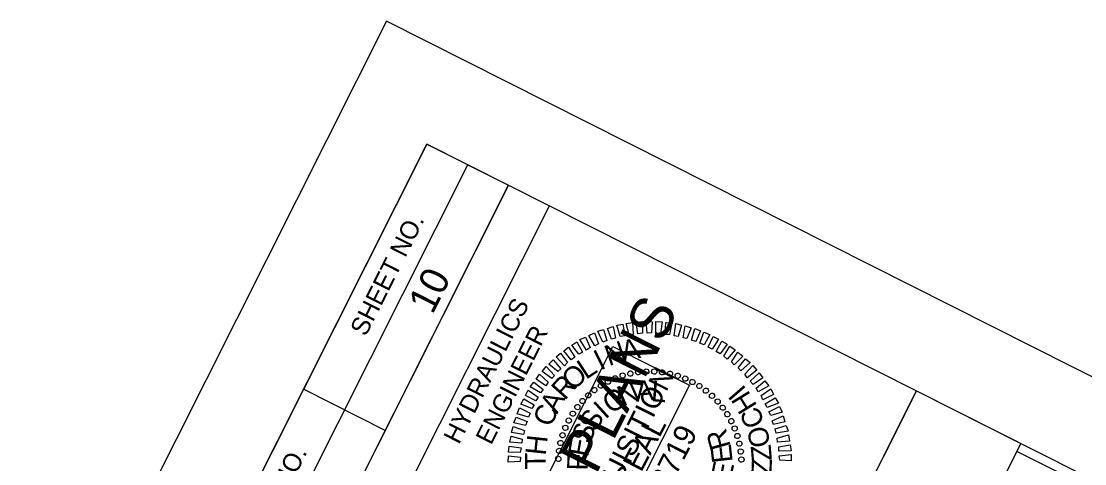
# Model space of a CAD drawing. Extents: x 2010322 to 2012069, y 441674 to 443687.
# Drawn here: x 2010986.8 to 2011277.9, y 443566.2 to 443687.1 of the extents above; entities that cross this region are included whole.
import ezdxf

# ---------------------------------------------------------------- set-up
doc = ezdxf.new("R2010")
doc.units = 0
for name, color, linetype in [('Sheet Clip Boundary CELL', 7, 'Continuous'), ('Sheet Data Field CELL', 7, 'Continuous'), ('Sheet Plan And Profile CELL', 7, 'Continuous'), ('Sheet Plot Border Outside CELL', 7, 'Continuous'), ('Sheet Professional Seal CELL', 7, 'Continuous'), ('Sheet Profile Grid Minor CELL', 7, 'Continuous'), ('Sheet Sticker Exception Certification CELL', 7, 'Continuous'), ('Sheet Sticker Incomplete CELL', 7, 'Continuous')]:
    doc.layers.add(name, color=color, linetype=linetype)

msp = doc.modelspace()

# ---------------------------------------------------------------- linework, layer by layer
at = {"layer": 'Sheet Clip Boundary CELL'}
msp.add_lwpolyline([(2011359.68, 441843.44), (2012033.06, 443180.92), (2011922.92, 443238.13), (2011759.16, 443078.9), (2011595.22, 443247.25), (2011606.93, 443258.94), (2011612.2, 443362.21), (2011388.82, 443474.46), (2011348.46, 443524.76), (2011259.26, 443569.48), (2011170.42, 443393.01), (2011067.41, 443444.87), (2010977.45, 443266.18), (2010917.88, 443296.17), (2010676.94, 442817.58), (2010544.65, 442554.81), (2010423.28, 442313.75), (2010551.1, 442249.4)], close=True, dxfattribs=at)
at = {"layer": 'Sheet Plan And Profile CELL'}
for p, q in [((2011019.05, 443469.21), (2011109.01, 443647.9)), ((2011030.22, 443463.59), (2011120.17, 443642.28)), ((2011064.12, 443586.53), (2011086.45, 443575.29))]:
    msp.add_line(p, q, dxfattribs=at)
for points in [[(2011097.8, 443653.54), (2010423.28, 442313.75), (2011361.14, 441841.59), (2012035.65, 443181.38)], [(2011007.84, 443474.86), (2011097.8, 443653.54), (2011120.17, 443642.28), (2011030.22, 443463.59)], [(2011086.37, 443547.34), (2011131.34, 443636.65), (2011231.82, 443586.07), (2011186.86, 443496.75)]]:
    msp.add_lwpolyline(points, close=True, dxfattribs=at)
at = {"layer": 'Sheet Plot Border Outside CELL'}
msp.add_lwpolyline([(2011304.77, 441674.04), (2012069.22, 443192.47), (2011086.71, 443687.11), (2010322.26, 442168.69)], close=True, dxfattribs=at)
at = {"layer": 'Sheet Professional Seal CELL'}
for p, q in [((2011151.37, 443590.28), (2011151.37, 443590.28)), ((2011153.52, 443590.88), (2011153.52, 443590.88)), ((2011155.64, 443591.21), (2011155.64, 443591.21)), ((2011157.86, 443591.38), (2011157.86, 443591.38)), ((2011160.05, 443591.4), (2011160.05, 443591.4)), ((2011162.19, 443591.21), (2011162.19, 443591.21)), ((2011164.34, 443590.8), (2011164.34, 443590.8)), ((2011166.48, 443590.17), (2011166.48, 443590.17)), ((2011145.41, 443587.57), (2011145.41, 443587.57)), ((2011147.34, 443588.62), (2011147.34, 443588.62)), ((2011149.33, 443589.57), (2011149.33, 443589.57)), ((2011168.54, 443589.47), (2011168.54, 443589.47)), ((2011170.53, 443588.53), (2011170.53, 443588.53)), ((2011172.42, 443587.41), (2011172.42, 443587.41)), ((2011141.94, 443584.9), (2011141.94, 443584.9)), ((2011143.64, 443586.28), (2011143.64, 443586.28)), ((2011174.19, 443586.13), (2011174.19, 443586.13)), ((2011175.86, 443584.78), (2011175.86, 443584.78)), ((2011139.02, 443581.66), (2011139.02, 443581.66)), ((2011140.37, 443583.34), (2011140.37, 443583.34)), ((2011177.42, 443583.21), (2011177.42, 443583.21)), ((2011178.8, 443581.51), (2011178.8, 443581.51)), ((2011137.74, 443579.9), (2011137.74, 443579.9)), ((2011180.09, 443579.74), (2011180.09, 443579.74)), ((2011135.68, 443576.01), (2011135.68, 443576.01)), ((2011136.62, 443578), (2011136.62, 443578)), ((2011181.14, 443577.81), (2011181.14, 443577.81)), ((2011182.1, 443575.82), (2011182.1, 443575.82)), ((2011134.98, 443573.96), (2011134.98, 443573.96)), ((2011182.81, 443573.78), (2011182.81, 443573.78)), ((2011133.94, 443569.67), (2011133.94, 443569.67)), ((2011134.35, 443571.81), (2011134.35, 443571.81)), ((2011183.4, 443571.63), (2011183.4, 443571.63)), ((2011183.73, 443569.51), (2011183.73, 443569.51)), ((2011133.75, 443567.52), (2011133.75, 443567.52)), ((2011183.91, 443567.29), (2011183.91, 443567.29)), ((2011158.84, 443566.31), (2011158.84, 443566.31))]:
    msp.add_line(p, q, dxfattribs=at)
for points in [[(2011153.16, 443601.41), (2011152.39, 443604.54), (2011154.11, 443604.74), (2011154.28, 443601.52)], [(2011155.58, 443601.65), (2011155.08, 443604.87), (2011156.84, 443605.05), (2011156.79, 443601.83)], [(2011158.13, 443601.82), (2011157.83, 443605.11), (2011159.5, 443604.99), (2011159.25, 443601.93)], [(2011160.5, 443601.75), (2011160.49, 443605.06), (2011162.21, 443604.92), (2011161.71, 443601.7)], [(2011163, 443601.5), (2011163.21, 443604.81), (2011164.85, 443604.6), (2011164.17, 443601.47)], [(2011165.51, 443601.13), (2011165.92, 443604.51), (2011167.53, 443604.03), (2011166.6, 443600.97)], [(2011143.74, 443598.37), (2011142.12, 443601.26), (2011143.69, 443601.93), (2011144.8, 443598.91)], [(2011145.98, 443599.37), (2011144.58, 443602.38), (2011146.19, 443602.91), (2011147.08, 443599.89)], [(2011148.35, 443600.2), (2011147.22, 443603.17), (2011148.83, 443603.71), (2011149.41, 443600.51)], [(2011150.75, 443600.95), (2011149.77, 443604.02), (2011151.45, 443604.35), (2011151.96, 443601.12)], [(2011167.92, 443600.59), (2011168.49, 443603.83), (2011170.14, 443603.33), (2011168.99, 443600.38)], [(2011170.27, 443599.91), (2011171.1, 443603.13), (2011172.69, 443602.5), (2011171.43, 443599.55)], [(2011172.55, 443599.1), (2011173.65, 443602.18), (2011175.21, 443601.51), (2011173.66, 443598.65)], [(2011139.4, 443596.08), (2011137.46, 443598.57), (2011138.89, 443599.53), (2011140.36, 443596.66)], [(2011141.48, 443597.22), (2011139.68, 443600.09), (2011141.2, 443600.77), (2011142.51, 443597.93)], [(2011174.8, 443598.02), (2011176.13, 443600.99), (2011177.65, 443600.23), (2011175.87, 443597.48)], [(2011177.01, 443596.85), (2011178.56, 443599.71), (2011179.99, 443598.88), (2011178.04, 443596.22)], [(2011135.48, 443592.96), (2011133.18, 443595.41), (2011134.35, 443596.39), (2011136.31, 443593.83)], [(2011137.34, 443594.55), (2011135.26, 443596.99), (2011136.59, 443598.06), (2011138.32, 443595.28)], [(2011179.04, 443595.55), (2011180.75, 443598.27), (2011182.18, 443597.33), (2011180, 443594.79)], [(2011181.14, 443594.05), (2011182.89, 443596.63), (2011184.25, 443595.56), (2011181.9, 443593.22)], [(2011133.66, 443591.36), (2011131.23, 443593.42), (2011132.37, 443594.58), (2011134.45, 443592.14)], [(2011182.99, 443592.39), (2011184.97, 443594.86), (2011186.28, 443593.81), (2011183.75, 443591.56)], [(2011184.8, 443590.64), (2011187, 443593), (2011188.09, 443591.72), (2011185.49, 443589.67)], [(2011130.36, 443587.48), (2011127.71, 443589.32), (2011128.67, 443590.68), (2011131.04, 443588.48)], [(2011132, 443589.51), (2011129.32, 443591.42), (2011130.44, 443592.75), (2011132.7, 443590.33)], [(2011186.31, 443588.75), (2011188.73, 443591.01), (2011189.78, 443589.64), (2011187.07, 443587.81)], [(2011128.93, 443585.51), (2011126.11, 443587.15), (2011127.12, 443588.49), (2011129.64, 443586.5)], [(2011187.92, 443586.83), (2011190.32, 443588.81), (2011191.36, 443587.44), (2011188.5, 443585.86)], [(2011127.67, 443583.35), (2011124.77, 443584.81), (2011125.55, 443586.26), (2011128.25, 443584.4)], [(2011189.3, 443584.79), (2011191.9, 443586.61), (2011192.7, 443585.09), (2011189.74, 443583.67)], [(2011190.41, 443582.55), (2011193.14, 443584.2), (2011194.01, 443582.7), (2011190.97, 443581.54)], [(2011125.64, 443578.88), (2011122.54, 443579.83), (2011123.12, 443581.44), (2011126.05, 443580.02)], [(2011126.54, 443581.23), (2011123.53, 443582.47), (2011124.32, 443583.92), (2011127.13, 443582.28)], [(2011191.43, 443580.35), (2011194.34, 443581.8), (2011195.01, 443580.23), (2011191.92, 443579.32)], [(2011124.83, 443576.6), (2011121.61, 443577.33), (2011122.22, 443578.87), (2011125.24, 443577.74)], [(2011192.34, 443577.94), (2011195.32, 443579.29), (2011195.79, 443577.66), (2011192.7, 443576.86)], [(2011124.24, 443574.21), (2011120.96, 443574.69), (2011121.41, 443576.37), (2011124.49, 443575.26)], [(2011193.16, 443575.68), (2011196.12, 443576.65), (2011196.65, 443575.04), (2011193.36, 443574.51)], [(2011123.75, 443571.78), (2011120.55, 443572.1), (2011120.84, 443573.68), (2011123.91, 443572.87)], [(2011193.65, 443573.19), (2011196.76, 443574.03), (2011197.09, 443572.36), (2011193.8, 443572.05)], [(2011123.36, 443569.23), (2011120.18, 443569.37), (2011120.32, 443570.98), (2011123.65, 443570.48)], [(2011194.13, 443570.82), (2011197.24, 443571.33), (2011197.51, 443569.74), (2011194.18, 443569.57)], [(2011123.31, 443566.79), (2011120.09, 443566.62), (2011120.16, 443568.32), (2011123.4, 443567.98)], [(2011194.26, 443568.29), (2011197.51, 443568.73), (2011197.52, 443566.99), (2011194.37, 443567.18)]]:
    msp.add_lwpolyline(points, close=True, dxfattribs=at)
for centre, major_axis in [((2011149.33, 443589.52), (-0.273, 0.666)), ((2011151.39, 443590.26), (-0.214, 0.688)), ((2011153.5, 443590.82), (-0.153, 0.704)), ((2011155.66, 443591.19), (-0.091, 0.714)), ((2011157.84, 443591.37), (-0.029, 0.719)), ((2011160.03, 443591.36), (0.034, 0.719)), ((2011162.21, 443591.17), (0.097, 0.713)), ((2011164.36, 443590.78), (0.159, 0.702)), ((2011166.47, 443590.2), (0.219, 0.686)), ((2011168.53, 443589.45), (0.278, 0.664)), ((2011143.65, 443586.27), (-0.436, 0.573)), ((2011145.44, 443587.52), (-0.384, 0.609)), ((2011147.34, 443588.6), (-0.33, 0.64)), ((2011170.5, 443588.51), (0.335, 0.637)), ((2011172.39, 443587.41), (0.389, 0.606)), ((2011174.18, 443586.15), (0.441, 0.57)), ((2011140.41, 443583.33), (-0.529, 0.488)), ((2011141.97, 443584.87), (-0.484, 0.533)), ((2011175.85, 443584.74), (0.488, 0.529)), ((2011139, 443581.66), (-0.57, 0.441)), ((2011177.39, 443583.18), (0.533, 0.484)), ((2011178.79, 443581.5), (0.573, 0.436)), ((2011136.64, 443577.98), (-0.637, 0.335)), ((2011137.74, 443579.87), (-0.606, 0.389)), ((2011180.04, 443579.71), (0.609, 0.384)), ((2011181.13, 443577.81), (0.64, 0.33)), ((2011135.7, 443576), (-0.664, 0.278)), ((2011182.05, 443575.82), (0.666, 0.273)), ((2011134.37, 443571.84), (-0.702, 0.159)), ((2011134.95, 443573.95), (-0.686, 0.219)), ((2011182.79, 443573.76), (0.688, 0.214)), ((2011183.34, 443571.65), (0.704, 0.153)), ((2011133.98, 443569.68), (-0.713, 0.097)), ((2011183.72, 443569.49), (0.714, 0.091)), ((2011133.79, 443567.5), (-0.719, 0.034)), ((2011183.9, 443567.31), (0.719, 0.029))]:
    msp.add_ellipse(centre, major_axis=major_axis, ratio=0.999708, dxfattribs=at)
at = {"layer": 'Sheet Sticker Exception Certification CELL'}
for p, q in [((2011141.85, 443407.39), (2011231.81, 443586.07)), ((2011231.82, 443586.07), (2011260.39, 443571.68)), ((2011260.37, 443571.69), (2011170.42, 443393.01))]:
    msp.add_line(p, q, dxfattribs=at)
at = {"layer": 'Sheet Sticker Incomplete CELL'}
msp.add_lwpolyline([(2011103.56, 443456.39), (2011082.57, 443466.96), (2011148.67, 443598.26), (2011169.66, 443587.69)], close=True, dxfattribs=at)

# ---------------------------------------------------------------- texts
at = {"layer": 'Sheet Data Field CELL'}
msp.add_text('10', height=7.75, rotation=63.277, dxfattribs=at).set_placement((2011099.33, 443606.76))
at = {"layer": 'Sheet Plan And Profile CELL'}
for s, height, p in [('SHEET NO.', 5, (2011081.06, 443600.73)), ('HYDRAULICS', 5, (2011106.58, 443571.25)), ('ENGINEER', 5, (2011115.39, 443571.07)), ('PROJECT REFERENCE NO.', 5.0001, (2011025.6, 443490.77))]:
    msp.add_text(s, height=height, rotation=63.277, dxfattribs=at).set_placement(p)
at = {"layer": 'Sheet Professional Seal CELL'}
for s, height, rotation, p in [('N', 5.64, 19.0959, (2011147.66, 443592.82)), ('A', 5.64, 11.8942, (2011151.62, 443594.13)), ('I', 5.64, 26.2972, (2011145.31, 443591.6)), ('O', 5.64, 40.6982, (2011137.72, 443585.96)), ('L', 5.64, 33.4979, (2011141.35, 443589.06)), ('R', 5.64, 47.8981, (2011135.54, 443583.3)), ('N', 5.64, 23.7536, (2011151.48, 443581.72)), ('A', 5.64, 5.0373, (2011155.08, 443583.09)), ('L', 5.64, 355.6779, (2011159.04, 443583.28)), ('A', 5.64, 62.2974, (2011133.47, 443579.64)), ('O', 5.64, 33.1105, (2011148.19, 443579.62)), ('C', 5.64, 69.4969, (2011131.96, 443575.98)), ('I', 5.64, 42.4666, (2011146.66, 443578.15)), ('S', 5.64, 61.1774, (2011144.1, 443574.63)), ('S', 5.64, 70.5326, (2011142.53, 443571.39)), ('SEAL', 5.998, 62.277, (2011153.96, 443558.86)), ('R', 5.64, 105.7584, (2011181.03, 443570.92)), ('H', 5.64, 83.8965, (2011130.33, 443568.29)), ('E', 5.64, 79.8881, (2011141.91, 443567.84)), ('E', 5.64, 96.4011, (2011181.53, 443566.7)), ('T', 5.64, 91.0968, (2011130.35, 443564.65)), ('F', 5.64, 89.2441, (2011141.82, 443564.3)), ('E', 5.64, 77.6888, (2011180.89, 443561.09))]:
    msp.add_text(s, height=height, rotation=rotation, dxfattribs=at).set_placement(p)
at = {"layer": 'Sheet Profile Grid Minor CELL'}
for s, height, rotation, p in [('I', 5.5, 130.8697, (2011185.42, 443586.57)), ('H', 5.5, 121.6249, (2011188.33, 443582.04)), ('C', 5.5, 112.7522, (2011190.41, 443577.3)), ('033719', 5.998, 63.277, (2011160, 443550.82)), ('O', 5.5, 102.0477, (2011191.9, 443571.25)), ('Z', 5.5, 94.9209, (2011192.26, 443567.11)), ('Z', 5.5, 87.7941, (2011192.1, 443562.96))]:
    msp.add_text(s, height=height, rotation=rotation, dxfattribs=at).set_placement(p)
at = {"layer": 'Sheet Sticker Incomplete CELL'}
for s, height, p in [('INCOMPLETE PLANS', 11.52, (2011097.14, 443469.65)), ('DO NOT USE FOR R/W ACQUISITION', 5.76, (2011104.81, 443469.42))]:
    msp.add_text(s, height=height, rotation=63.277, dxfattribs=at).set_placement(p)

doc.saveas('drawing.dxf')
